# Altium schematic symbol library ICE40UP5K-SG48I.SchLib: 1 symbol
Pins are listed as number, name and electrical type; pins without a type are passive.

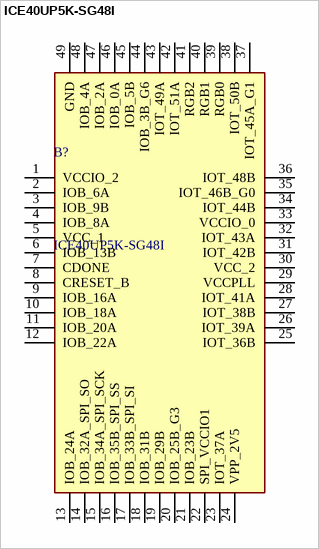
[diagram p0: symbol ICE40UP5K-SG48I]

## ICE40UP5K-SG48I
designator B?
FPGA - Field Programmable Gate Array iCE40-UltraPlus, 5280 LUTs, 1.2V; Manufacturer_Name: Lattice Semiconductor; Geometry.Height: 1mm
footprint QFN50P700X700X100-49N-D
pins: 1 VCCIO_2, 2 IOB_6A, 3 IOB_9B, 4 IOB_8A, 5 VCC_1, 6 IOB_13B, 7 CDONE, 8 CRESET_B, 9 IOB_16A, 10 IOB_18A, 11 IOB_20A, 12 IOB_22A, 13 IOB_24A, 14 IOB_32A_SPI_SO, 15 IOB_34A_SPI_SCK, 16 IOB_35B_SPI_SS, 17 IOB_33B_SPI_SI, 18 IOB_31B, 19 IOB_29B, 20 IOB_25B_G3, 21 IOB_23B, 22 SPI_VCCIO1, 23 IOT_37A, 24 VPP_2V5, 25 IOT_36B, 26 IOT_39A, 27 IOT_38B, 28 IOT_41A, 29 VCCPLL, 30 VCC_2, 31 IOT_42B, 32 IOT_43A, 33 VCCIO_0, 34 IOT_44B, 35 IOT_46B_G0, 36 IOT_48B, 37 IOT_45A_G1, 38 IOT_50B, 39 RGB0, 40 RGB1, 41 RGB2, 42 IOT_51A, 43 IOT_49A, 44 IOB_3B_G6, 45 IOB_5B, 46 IOB_0A, 47 IOB_2A, 48 IOB_4A, 49 GND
